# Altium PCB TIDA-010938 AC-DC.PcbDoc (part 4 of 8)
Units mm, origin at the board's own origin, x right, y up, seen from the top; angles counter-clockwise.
Board outline 280 x 180.15 mm, 4 copper layers (Top Layer, Layer 1, Layer 2, Bottom Layer), stack 1.787 mm thick; 723 components, 427 nets, 2244 pads, 2295 vias.
Unrouted connection lines stored in the file: 17.
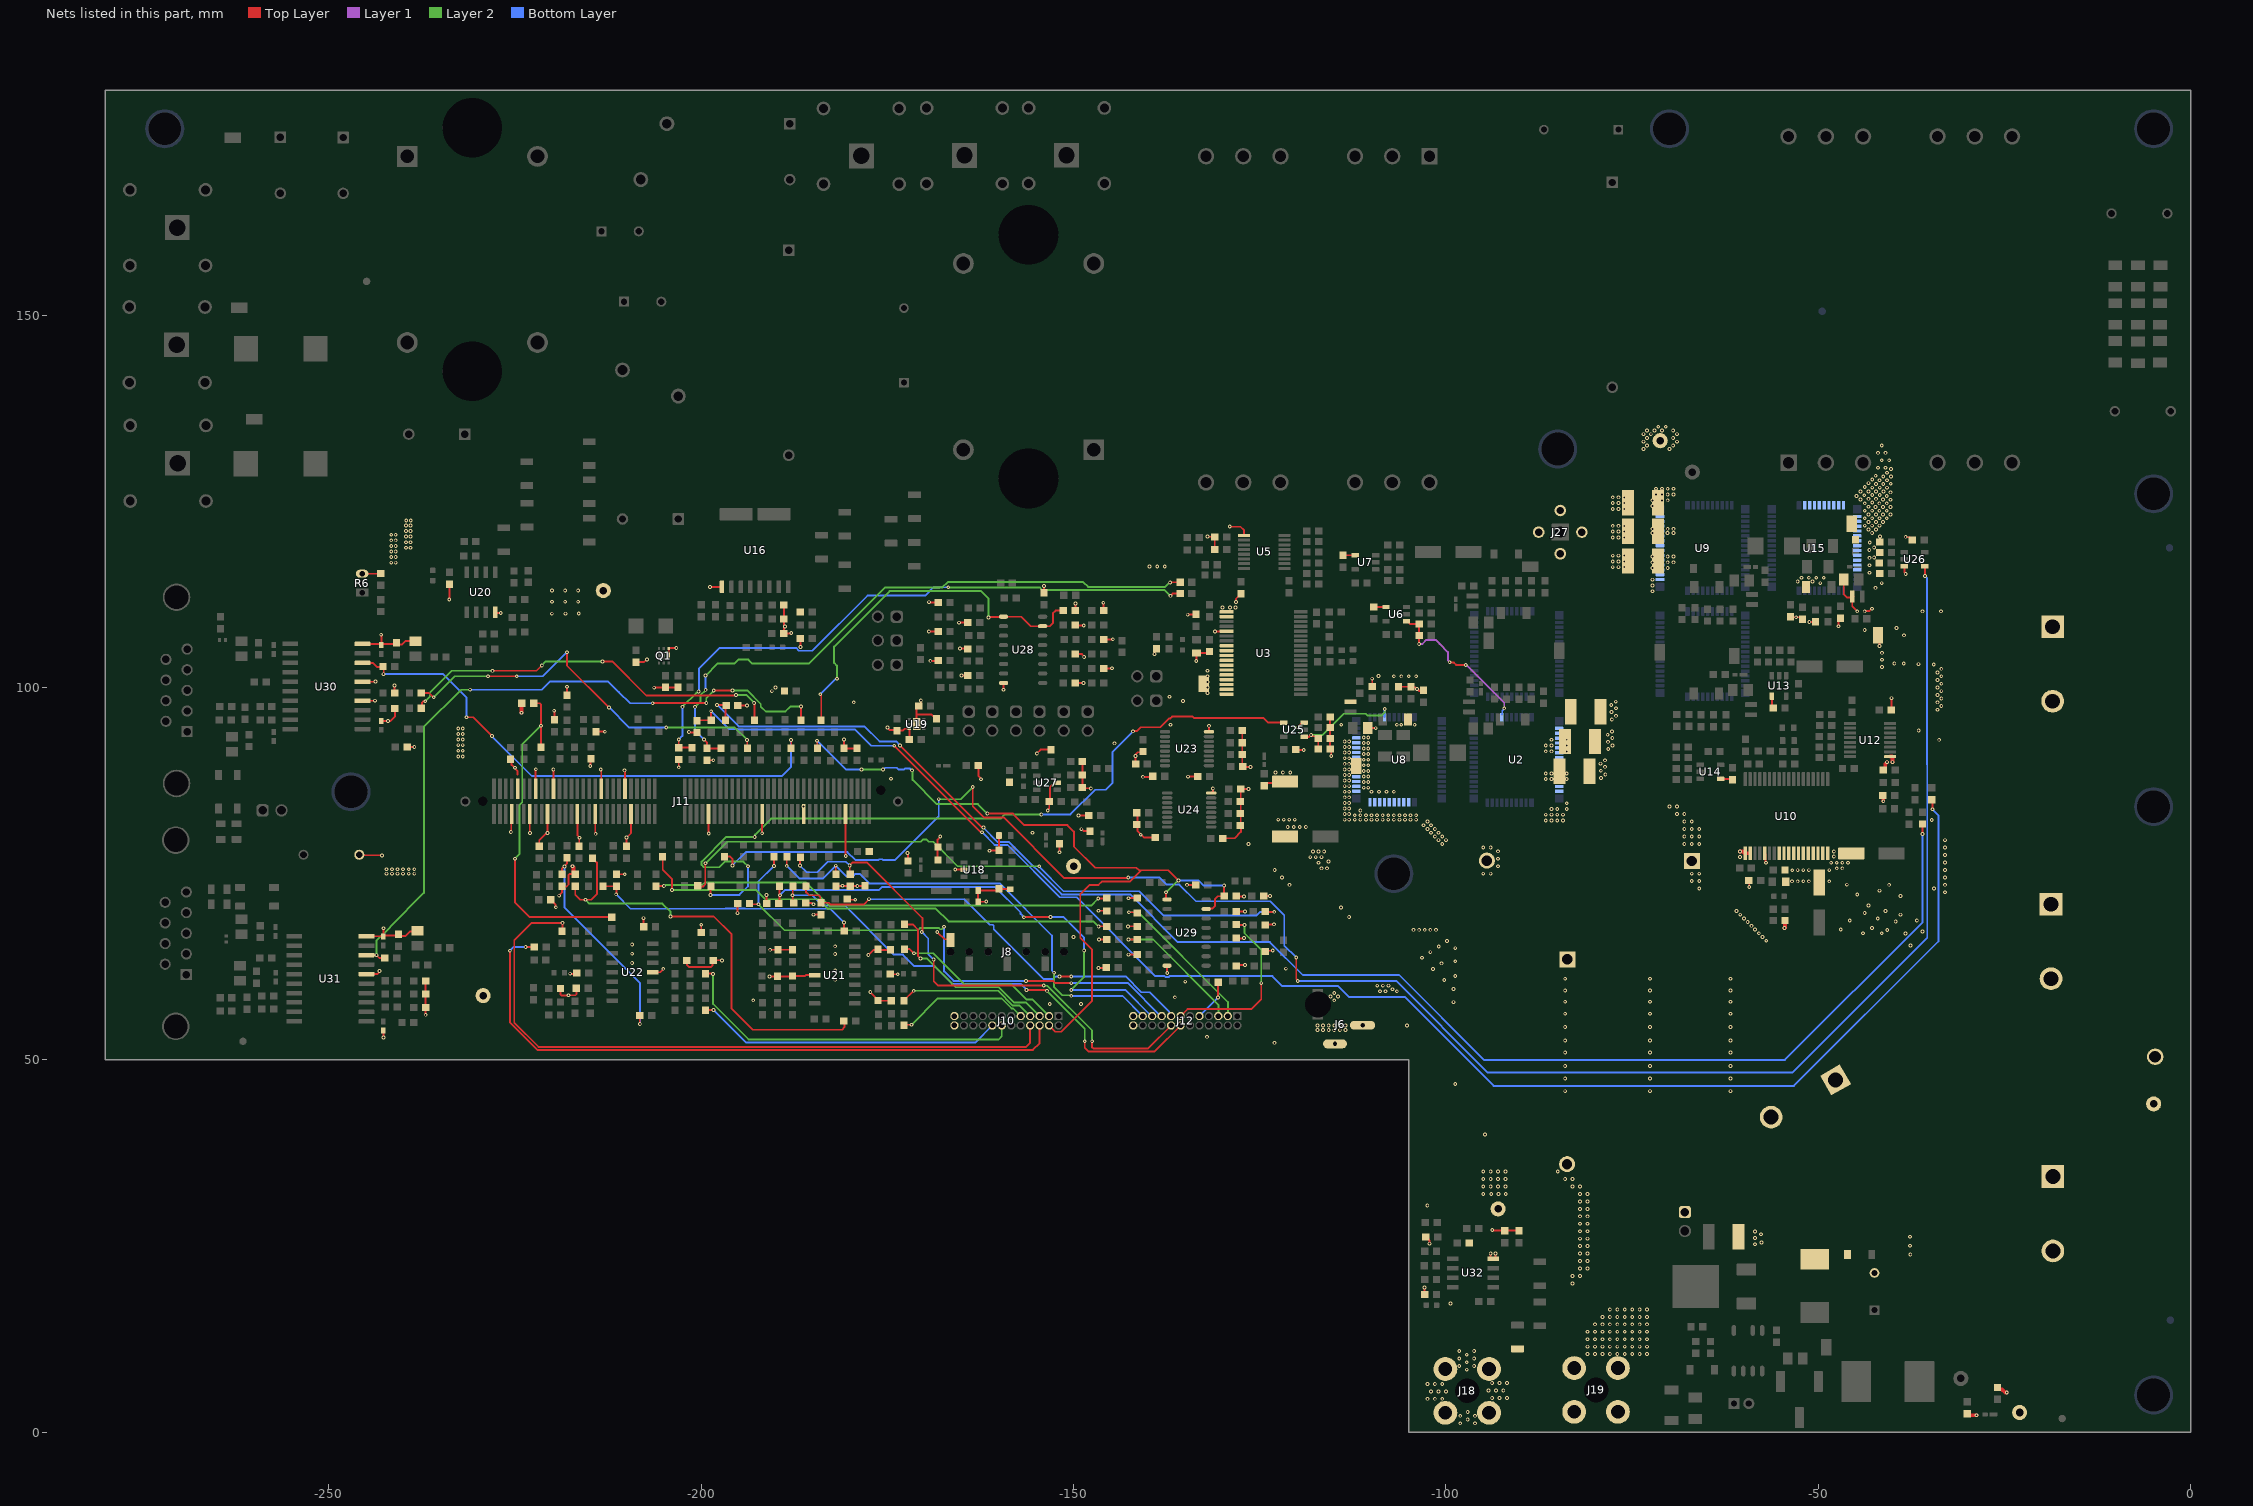
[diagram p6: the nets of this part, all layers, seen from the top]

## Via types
v1: diameter 0.508, hole 0.254, Top Layer to Bottom Layer, tented both sides, 2041 vias
v2: diameter 0.508, hole 0.254, Top Layer to Bottom Layer, 252 vias
v3: diameter 0.5, hole 0.2, Top Layer to Bottom Layer, 2 vias

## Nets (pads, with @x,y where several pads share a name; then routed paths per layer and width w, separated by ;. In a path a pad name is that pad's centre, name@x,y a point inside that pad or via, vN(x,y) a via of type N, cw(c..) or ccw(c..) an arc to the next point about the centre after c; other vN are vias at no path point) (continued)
Batt_L1_Buff: J12.9 R279.2 | length 5.6
  Top Layer w0.25: v1(-130.625,58.365) R279.2@-130.625,60.425
  Bottom Layer w0.25: J12.9@-133.095,55.89 -130.625,58.36 v1(-130.625,58.365)
Batt_L2: R197.2 R282.1 | length 87.2
  Top Layer w0.25: R197.2@-200.479,73.321 R197.2@-200.45,73.35 -200.4,73.3 -199.7,73.3 -199.44,73.56 -199.44,76.281 -199.421,76.3 v1@-199.4,76.3 ; R282.1@-124.249,69.9 -124.225,69.875 -123.125,69.875 v1@-123.075,69.825
  Layer 2 w0.25: v1(-199.4,76.4) -196.517,79.283 -170.516,79.283 -170.194,79.604 -169.756,79.604 -169.434,79.283 -168.859,79.283 -165.577,76 v1(-154.6,76)
  Bottom Layer w0.25: v1@-154.6,75.9 -151.348,72.648 -141.2,72.648 -137.948,69.396 -125.409,69.396 -124.93,69.875 v1(-123.05,69.875)
Batt_L2_Buff: J12.13 R286.2 | length 23.7
  Top Layer w0.25: J12.13@-135.635,55.89 -134.7,56.825 -126.125,56.825 -124.8,58.15 v1(-124.8,60.3) ; R286.2@-128.075,68.125 v1(-127.05,68.125)
  Layer 2 w0.25: v1(-127.05,68.125) -127.05,67.023 -124.8,64.773 v1(-124.8,60.3)
Boost_S1: R198.1 R263.1 | length 62.2
  Top Layer w0.25: R198.1@-206.05,73.325 -206.025,73.35 -205.05,73.35 v1@-205,73.3 ; v1(-146.675,71.675) R263.1@-145.65,71.675
  Layer 2 w0.25: v1(-205,73.35) -204.93,73.35 -204.78,73.5 -199.818,73.5 -199.508,73.81 -185.91,73.81 -182.821,70.721 -147.629,70.721 -146.75,71.6 v1@-146.7,71.6
Boost_S1_Buff: J12.3 R259.2 | length 21
  Top Layer w0.25: v1(-142.575,69.825) -141.75,69.825 R259.2@-141.725,69.85
  Layer 2 w0.25: v1(-142.575,69.825) -141.337,69.825 -129.285,57.773 -129.285,56.06 J12.3@-129.2,55.975
Boost_S2: R199.1 R267.1 | length 65.5
  Top Layer w0.25: R199.1@-205.2,77.25 -205.15,77.2 -205.15,75.497 -203.9,74.247 v1(-203.9,72.8) ; v1@-146.7,67.9 -146.663,67.937 R267.1@-145.531,67.937
  Layer 2 w0.25: v1(-203.9,72.8) -203.871,72.829 -192.652,72.829 -191.394,71.571 -184.237,71.571 -182.987,70.321 -168.5,70.321 -166.779,68.6 -147.325,68.6 v1(-146.625,67.9)
Boost_S2_Buff: J12.5 R264.2 | length 18.1
  Top Layer w0.25: v1(-142.625,66.175) -141.7,66.175 R264.2@-141.675,66.2
  Layer 2 w0.25: v1@-142.55,66.175 -139.33,66.175 -130.555,57.4 J12.5@-130.555,55.89
CAN_RX: R213.2 R314.1 | length 53.4
  Top Layer w0.25: R314.1@-237.544,99.238 -236.515,99.238 -235.956,98.679 v1(-235.886,98.679) ; v1(-228.588,101.5) v1(-224.75,101.5) ; v1(-218,104.729) -218,102.943 v1(-212.374,97.317) ; v1@-193.8,92.9 -193.8,91.882 R213.2@-193.782,91.864
  Layer 2 w0.25: v1(-235.886,98.679) -233.065,101.5 v1(-228.588,101.5) ; v1@-204.6,94.6 -204.596,94.604 -195.479,94.604 v1(-193.825,92.95)
  Bottom Layer w0.25: v1(-224.75,101.5) -221.25,101.5 -218.021,104.729 v1(-218,104.729) ; v1@-212.4,97.4 -209.617,94.617 v1(-204.674,94.617)
CAN_TX: R215.2 R311.1 | length 52.7
  Top Layer w0.25: R311.1@-237.544,97.206 -237.48,97.27 -237.48,97.928 -237.313,98.096 -237.078,98.096 v1(-237.029,98.146) ; v1(-228.012,102.235) -222.094,102.235 v1(-221.383,102.946) ; v1(-213.25,103.5) -211.913,103.5 -207.334,98.921 -195.561,98.921 -195.532,98.951 -195.349,98.951 v1(-195.3,99) ; R215.2@-192.816,95.598 -192.816,97.884 v1@-192.8,97.9
  Layer 2 w0.25: v1(-237.029,98.146) -236.415,98.76 -236.415,99.305 -233.47,102.25 -228.027,102.25 v1(-228.012,102.235) ; v1(-221.383,102.946) -220.829,103.5 v1(-213.25,103.5) ; v1(-195.3,99) -193.957,99 v1(-192.874,97.917)
CS_Batt1: C146.1 R141.2 R179.2 | length 45.6
  Top Layer w0.25: v1(-225,77) -225,71.156 -223.186,69.342 -223.019,69.175 R141.2@-212.175,69.175 ; C146.1@-222.45,97.875 -221.646,97.875 -221.5,97.729 v1(-221.5,94.853) -221.5,91.978 R179.2@-221.501,91.977
  Layer 2 w0.25: v1(-225,77) -224.4,77.6 -224.4,84.205 -224,84.605 -224,92.353 v1(-221.5,94.853)
CS_Batt1+: J10.6 R139.1 | length 88.4
  Top Layer w0.25: v1(-225.675,64.65) -225.675,55.034 -221.991,51.35 -155.45,51.35 -154.555,52.245 J10.6@-154.555,54.62 ; v1@-223.45,65.175 -223.448,65.173 R139.1@-222.397,65.173
  Bottom Layer w0.25: v1(-225.675,64.65) -225.15,65.175 v1@-223.575,65.175
  other v1: -223.55,65.175
CS_Batt1-: J10.8 R143.1 | length 92.7
  Top Layer w0.25: R143.1@-218.657,67.276 -218.6,67.333 v1@-218.6,68.275 ; v1@-218.65,68.45 -218.7,68.4 -222.725,68.4 -225.075,66.05 -225.075,55 -221.825,51.75 -156.35,51.75 -155.825,52.275 J10.8@-155.825,54.62
  other v1: -218.6,68.4
CS_Batt2: C158.1 R161.2 R184.2 | length 28.7
  Top Layer w0.25: C158.1@-218.675,74.925 -218.488,74.925 C158.1@-218.449,74.886 ; C158.1@-218.675,75.3 -218.675,75.675 -218.025,76.325 R184.2@-218.025,77.125 ; R161.2@-208.226,55.933 -208.226,54.926 v1@-208.2,54.9
  Bottom Layer w0.25: v1(-218.35,75.975) -218.35,70.463 -208.225,60.337 -208.225,54.85 v1@-208.2,54.825
  other v1: -208.225,54.825
CS_Batt2+: J10.14 R159.1 | length 47.4
  Top Layer w0.25: R159.1@-199.435,61.58 -198.43,61.58 v1(-198.4,61.55)
  Layer 2 w0.25: v1@-198.425,61.525 -198.4,61.5 -198.4,57.523 -193.614,52.737 -160.063,52.737 -159.635,53.165 J10.14@-159.635,54.62
CS_Batt2-: J10.16 R163.1 | length 41.3
  Top Layer w0.25: R163.1@-199.435,56.678 -198.322,56.678 v1@-198.3,56.7
  Bottom Layer w0.25: v1@-198.359,56.616 -198.241,56.616 -193.95,52.325 -163.2,52.325 J10.16@-160.905,54.62
  other v1: -198.325,56.7
CS_Boost1: C145.2 R140.2 R187.1 | length 59.3
  Top Layer w0.25: C145.2@-216.85,73.375 C145.2@-216.896,73.329 -216.896,72.146 -216.25,71.5 -214.75,71.5 -213.996,72.254 -213.996,76.487 -214.585,77.076 R187.1@-214.585,77.101 ; v1(-204.088,69.25) -198.3,69.25 -195.9,66.85 -195.9,56.884 -193.066,54.05 -181.075,54.05 -180.75,54.375 -180.75,55.423 R140.2@-180.801,55.474
  Layer 2 w0.25: v1(-215.5,71.5) -214.993,70.993 -205.203,70.993 -204.089,69.879 v1(-204.088,69.25)
CS_Boost1+: J10.7 R3.1 | length 18.9
  Top Layer w0.25: R3.1@-172.775,57.95 -172.775,57.975 -171.475,59.275 v1(-171.45,59.275)
  Layer 2 w0.25: v1(-171.45,59.275) -160.128,59.275 -158.153,57.3 -157.235,57.3 J10.7@-155.825,55.89
CS_Boost1-: J10.9 R4.1 | length 18.1
  Top Layer w0.25: R4.1@-172.75,54.625 -172.65,54.725 v1(-171.75,54.725)
  Layer 2 w0.25: v1@-171.725,54.725 -168.2,58.25 -159.669,58.25 -158.319,56.9 -158.105,56.9 J10.9@-157.095,55.89
CS_Boost2: C151.2 R150.2 R188.1 | length 36
  Top Layer w0.25: R188.1@-213.153,73.316 C151.2@-211.491,73.316 ; v1@-211.375,72.25 C151.2@-211.375,73.316 ; v1(-180.8,68.45) -180.8,67.55 R150.2@-180.65,67.4
  Bottom Layer w0.25: v1(-211.4,72.225) -209.475,70.3 -196.72,70.3 -196.717,70.303 -194.079,70.303 -194.076,70.3 -190.123,70.3 -182.65,70.3 -180.85,68.5 v1@-180.85,68.475
CS_Boost2+: J10.3 R137.1 | length 23.1
  Top Layer w0.25: R137.1@-172.7,64.875 -171.983,64.875 v1(-171.433,64.325)
  Layer 2 w0.25: v1(-171.433,64.325) -168.825,64.325 -164.659,60.159 -158.359,60.159 -156.3,58.1 -155.495,58.1 J10.3@-153.285,55.89
CS_Boost2-: J10.5 R138.1 | length 25.3
  Top Layer w0.25: R138.1@-172.7,68.2 -171.6,68.2 -170.904,67.504 -170.904,63.954 v1(-170.55,63.6)
  Layer 2 w0.25: v1(-170.55,63.6) -169.648,63.6 -165.807,59.759 -160.046,59.759 -157.987,57.7 -156.365,57.7 J10.5@-154.555,55.89
"DC Bus+": C2.2 C3.2 C4.2 C5.2 C30.1 C31.1 C46.1 C76.1 C88.1 C90.1 C241.2 C242.2 J7.1 J18.1 R108.1 TP13.1 U2.2 U2.3 U2.4 U2.5 U2.6 U2.7 U2.8 U2.9 U2.10 U2.11 U2.12 U2.13 U2.14 U2.15 U9.2 U9.3 U9.4 U9.5 U9.6 U9.7 U9.8 U9.9 U9.10 U9.11 U9.12 U9.13 U9.14 U9.15
  other v1: -98.089,1.214 -96.089,1.214 -97.089,1.714 -98.089,2.214 -96.089,2.214 -97.089,2.714 -102.5,4.5 -101.5,4.5 -100.5,4.5 -93.802,4.625 -92.802,4.625 -91.802,4.625 -102,5.5 -101,5.5 -100,5.5 -94.302,5.625 -93.302,5.625 -92.302,5.625 -102.5,6.5 -101.5,6.5 -100.5,6.5 -93.802,6.625 -92.802,6.625 -91.802,6.625 -97.214,8.411 -98.214,8.911 -96.214,8.911 -97.214,9.411 -98.214,9.911 -96.214,9.911 -97.214,10.411 -98.214,10.911 -96.214,10.911 -83,20 -83,21 -82,21 -82,22 -81,22 -82,23 -81,23 -82,24 -81,24 -82,25 -81,25 -82,26 -81,26 -82,27 -81,27 -82,28 -81,28 -82,29 -81,29 -82,30 -81,30 -82,31 -81,31 -82,32 -81,32 -83,33 -82,33 -84,34 -83,34 -85,35 -95,75 -94,75 -93,76 -93,77 -93,78 -95,78.5 -94,78.5 -86.61,82.15 -85.835,82.15 -85.06,82.15 -84.285,82.15 -86.61,82.925 -85.835,82.925 -85.06,82.925 -84.285,82.925 -85.835,83.7 -85.06,83.7 -83.785,83.7 -83.785,84.45 -86.61,87.7 -85.835,87.7 -83.785,87.7 -86.61,88.45 -85.835,88.45 -83.785,88.45 -86.61,91.425 -85.835,91.425 -83.785,91.425 -86.61,92.2 -85.835,92.2 -83.785,92.2 -85.835,92.975 -83.785,92.975 -72.29,112.921 -72.29,113.696 -72.29,114.471 -72.29,116.021 -70.24,116.021 -72.29,116.796 -70.24,116.796 -69.465,116.796 -72.29,117.571 -70.24,117.571 -69.465,117.571 -72.3,120.725 -70.25,120.725 -69.45,120.725 -72.29,121.296 -70.24,121.296 -69.465,121.296 -72.29,124.371 -72.29,125.121 -71.015,125.121 -70.24,125.121 -71.79,125.896 -71.015,125.896 -70.24,125.896 -69.465,125.896 -71.79,126.671 -71.015,126.671 -70.24,126.671 -69.465,126.671
"DC Bus-": C1.2 C2.1 C3.1 C4.1 C5.1 C7.1 C9.1 C10.2 C18.1 C22.2 C23.1 C29.1 C30.2 C31.2 C36.1 C37.1 C38.2 C41.1 C42.1 C46.2 C49.2 C50.1 C51.1 C52.1 C53.1 C54.2 C55.1 C56.1 C64.1 C67.2 C68.1 C76.2 C81.2 C82.1 C83.1 C84.1 C86.1 C87.1 C88.2 C90.2 C92.1 C93.1 C94.2 C95.1 C96.1 C97.1 C98.1 C99.2 C101.1 C105.2 C107.1 C108.1 C109.2 C110.2 C111.2 C112.1 C113.1 C114.2 C115.2 C118.2 C119.2 C120.2 C121.2 C122.1 C123.1 C124.2 C125.1 C126.2 C127.1 C128.1 C129.2 C130.1 C131.1 C132.1 C133.1 C134.1 C135.1 C136.1 C137.1 C138.2 C141.1 C142.1 C145.1 C146.2 C150.2 C151.1 C152.1 C156.2 C157.1 C158.2 C161.1 C162.2 C163.1 C164.1 C165.1 C167.1 C168.1 C169.2 C170.1 C171.1 C172.1 C173.1 C174.1 C175.1 C176.2 C177.1 C178.1 C179.1 C180.1 C181.1 C182.2 C185.2 C186.2 C189.1 C190.1 C191.2 C192.1 C193.1 C194.1 C195.2 C196.1 C197.2 C199.1 C200.1 C201.1 C202.1 C203.2 C204.1 C206.1 C208.1 C209.1 C214.1 C215.2 C216.2 C218.1 C219.1 C222.2 C229.2 C230.1 C231.1 C232.1 C234.1 C235.1 C238.2 C239.2 C241.1 C242.1 C251.2 C252.2 C253.1 C254.1 C255.1 C256.1 D19.2 D20.2 J6.2 J6.3 J8.7 J10.23 J10.24 J11.7 J11.10 J11.13 J11.16 J11.19 J11.22 J11.29 J11.35 J11.38 J11.46 J11.47 J11.65 J11.83 J11.97 J11.111 J12.23 J12.24 J19.1 J27.2 J27.3 J27.4 J27.5 L5.1 L9.1 Q1.4 Q1.7 R2.2 R6.2 R14.1 R16.1 R40.1 R43.1 R48.1 R50.2 R68.2 R70.1 R74.1 R76.1 R90.2 R92.1 R100.2 R101.1 R102.1 R106.2 R107.1 R115.1 R119.2 R133.1 R147.1 R157.1 R167.1 R172.2 R177.1 R202.1 R252.1 R253.1 R254.1 R256.1 R297.1 R298.1 R299.1 R300.1 R301.1 R302.1 R303.1 R304.1 R305.1 R306.1 R307.1 R308.1 R335.1 R336.1 R337.1 R338.1 TP2.1 TP3.1 TP11.1 TP12.1 TP14.1 TP15.1 TP16.1 TP19.1 TP20.1 TP21.1 TP22.1 U3.1 U3.2 U3.5 U3.8 U3.9 U3.10 U3.11 U3.12 U3.13 U3.14 U3.15 U3.16 U3.17 U3.18 U5.9 U8.18 U8.19 U8.20 U8.21 U8.22 U8.23 U8.24 U8.25 U8.26 U8.28 U8.29 U8.30 U8.31 U8.32 U8.33 U8.34 U8.35 U8.36 U8.37 U8.38 U8.39 U10.1 U10.2 U10.5 U10.8 U10.9 U10.10 U10.11 U10.12 U10.13 U10.14 U10.15 U10.16 U10.17 U10.18 U12.9 U15.18 U15.19 U15.20 U15.21 U15.22 U15.23 U15.24 U15.25 U15.26 U15.28 U15.29 U15.30 U15.31 U15.32 U15.33 U15.34 U15.35 U15.36 U15.37 U15.38 U15.39 U16.3 U18.2 U19.3 U19.7@-171.06,95.076 U20.4 U21.11 U22.11 U23.8 U24.8 U25.3 U26.3 U27.2 U28.8 U29.8 U30.4 U30.6 U30.10 U31.6 U31.10 U32.4 | length 331.7
  Top Layer w0.25: C1.2@-245.916,77.54 -245.85,77.474 -242.899,77.474 v1(-242.85,77.425) ; R6.2@-245.5,115.27 -243.03,115.27 C10.2@-243,115.3 ; U30.4@-245.456,98.222 -243.903,98.222 v1@-243.9,98.225 ; U30.6@-245.456,100.762 -243.838,100.762 v1@-243.8,100.8 ; U30.10@-245.456,105.842 -243.078,105.842 C195.2@-242.916,105.68 ; U31.6@-244.92,61.519 -243.481,61.519 v1@-243.1,61.9 ; U31.10@-244.92,66.599 -242.693,66.599 C216.2@-242.658,66.564 ; C197.2@-242.975,95.4 -242.875,95.5 -241.675,95.5 -241.1,96.075 ; v1@-242.925,107.1 -242.916,107.091 C195.2@-242.916,105.68 ; v1@-242.675,53.025 -242.658,53.042 C222.2@-242.658,53.934 ; v1@-242.675,67.525 -242.658,67.508 C216.2@-242.658,66.564 ; v1@-241.175,100.15 -241.175,99.309 C219.1@-241.1,99.234 ; C218.1@-241.1,97.169 -241.075,97.144 -241.075,96.125 ; C189.1@-241.075,105.875 -241.133,105.817 -242.779,105.817 C195.2@-242.916,105.68 ; C189.1@-240.873,105.817 -240.806,105.75 -240.175,105.75 -239.675,106.25 C191.2@-238.6,106.25 ; C214.1@-240.676,66.701 -242.521,66.701 C216.2@-242.658,66.564 ; C214.1@-240.615,66.701 -240.564,66.65 -239.675,66.65 -239.075,67.25 C215.2@-238.075,67.25 ; R50.2@-239.45,92 v1(-238.5,92) ; v1@-237,56.1 -236.99,56.11 C235.1@-236.99,57.041 ; C235.1@-236.99,57.16 C232.1@-236.99,58.819 C234.1@-236.99,60.597 ; v1(-233.803,111.811) -233.778,111.836 C230.1@-233.778,113.868 ; U20.4@-227.645,109.675 U20.4@-227.645,109.825 ; U20.4@-227.645,110.075 U20.4@-227.645,109.825 ; v1(-226.9,110) -227.47,110 U20.4@-227.645,109.825 ; C133.1@-225.565,90.339 -225.435,90.209 -225.435,89.61 -224.65,88.825 -224.65,88.325 ; v1(-225.539,80.589) -225.49,80.639 -225.49,82.915 J11.7@-225.407,82.998 ; J11.13@-223.007,82.998 -223.007,80.482 v1@-223,80.475 ; v1@-222.225,88.9 -222.207,88.882 J11.16@-222.207,86.398 ; C152.1@-221.725,78.7 -221.725,79.475 -220.799,80.401 -220.744,80.401 -220.7,80.445 v1@-220.7,80.5 ; v1@-220.607,80.507 J11.19@-220.607,82.998 ; C92.1@-220.2,71.5 -220.175,71.5 -219.549,70.874 -219.549,70.549 v1(-219.5,70.5) ; J11.22@-219.807,86.398 -219.807,88.918 v1@-219.8,88.925 ; C112.1@-219.698,95.672 -219.675,95.695 v1@-219.675,96.825 ; v1(-219.05,72.05) -219.05,72.075 -218.675,72.45 C158.2@-218.675,73.325 -218.6,73.25 -218.096,73.25 -217.8,73.546 -217.8,74.8 -217.65,74.95 C145.1@-217.25,74.95 ; R147.1@-218.873,59.576 -218.873,58.771 -218.727,58.625 -218.42,58.625 ; -218.419,58.626 v1@-217.925,58.626 ; C107.1@-217.975,98.975 -218,99 -218,100.075 v1@-217.975,100.1 ; v1(-217.8,58.675) -216.871,58.675 -216.725,58.821 -216.725,59.268 -216.6,59.393 C150.2@-216.6,59.425 ; v1@-217.6,61.525 -216.821,61.525 C142.1@-216.696,61.65 ; J11.29@-216.607,82.998 -216.607,80.177 -216.325,79.895 v1@-216.325,79.85 ; C157.1@-216.363,78.701 v1@-216.363,79.825 ; v1@-214.854,89.46 -214.854,90.371 C132.1@-214.8,90.425 ; J11.35@-214.207,82.998 -214.207,80.482 v1@-214.2,80.475 ; C134.1@-214.099,94.07 -212.97,94.07 v1@-212.95,94.05 ; J11.38@-213.407,86.398 -213.407,88.893 v1@-213.4,88.9 ; C151.1@-211.375,74.916 -210.334,74.916 v1@-210.325,74.925 ; J11.46@-210.207,86.398 -210.207,88.793 v1@-210.2,88.8 ; C164.1@-210.013,78.701 -210,78.714 v1@-210,79.8 ; v1@-209.95,79.925 -209.925,79.925 -209.407,80.443 J11.47@-209.407,82.998 ; C105.2@-208.75,103.4 -207.67,103.4 -207.32,103.75 v1(-207.25,103.75) ; C165.1@-207.718,67.871 -207.718,68.882 v1@-207.7,68.9 ; U22.11@-206.504,61.775 -205.475,61.775 v1@-205.05,62.2 ; v1(-206.3,99.975) -204.8,99.975 C114.2@-204.775,100 R90.2@-203.225,100 ; Q1.7@-204.35,104.345 Q1.4@-204.35,105.2 ; Q1.4@-204.35,105.225 -204.35,105.25 -204.325,105.275 v1@-203.3,105.275 ; R90.2@-203.175,100.05 R90.2@-203.125,100 ; v1(-203,89.275) -202.997,89.278 C37.1@-202.997,90.326 ; C163.1@-201.937,63.32 -201.9,63.283 -201.9,62.771 -201.579,62.45 -198.7,62.45 -198.45,62.7 -198.45,63.05 R172.2@-198.475,63.075 ; v1@-201.668,94.027 -201.591,93.95 C83.1@-200.575,93.95 ; C161.1@-199.981,67.13 -199.981,68.169 v1@-199.975,68.175 ; C36.1@-199.2,90.25 -199.174,90.224 v1(-198.359,90.224) ; J11.65@-199.007,82.998 -199.007,80.457 v1@-199,80.45 ; v1(-198.8,113.5) -197.211,113.5 U16.3@-197.195,113.516 ; R172.2@-198.381,63.32 -198.326,63.375 v1@-197.225,63.375 ; v1(-195.1,69.7) C136.1@-195.1,71 ; C82.1@-195.05,97.55 -195.025,97.575 v1(-193.825,97.575) ; v1@-191.825,80.425 -191.807,80.443 J11.83@-191.807,82.998 ; v1(-191.2,72.125) -191.2,71.25 C137.1@-191.175,71.225 ; v1@-190.8,64.8 -190.781,64.781 -187.781,64.781 C156.2@-187.725,64.725 ; v1@-190.75,61.275 -190.75,61.244 -190.706,61.2 -187.805,61.2 C162.2@-187.738,61.267 -186.058,61.267 -185.925,61.4 -185.325,61.4 U21.11@-185.3,61.425 ; C111.2@-188.89,107.263 -187.988,107.263 v1@-187.975,107.25 ; C111.2@-188.877,107.373 v1@-188.877,108.189 ; C109.2@-188.877,111.051 v1@-188.877,108.189 ; v1(-188.75,108.189) v1@-188.877,108.189 ; v1(-186.65,105.45) -186.65,106.5 C115.2@-186.525,106.625 ; v1(-186.25,84) -186.228,83.978 -186.228,83.019 J11.97@-186.207,82.998 ; C130.1@-185.975,71.075 -185.145,71.075 -184.97,70.9 v1(-184.9,70.9) ; v1(-184.9,69.5) C135.1@-183.9,69.5 ; C231.1@-181.9,73.325 v1@-180.95,73.325 ; v1@-180.975,73.35 v1@-180.95,73.325 ; v1(-180.825,93) -180.825,92 C182.2@-180.775,91.95 ; C182.2@-180.775,91.826 -179.251,91.826 C181.1@-179.151,91.726 ; v1@-180.675,77.425 -180.66,77.425 -180.591,77.494 -180.591,82.982 J11.111@-180.607,82.998 ; C108.1@-180.4,71.6 -180.3,71.5 v1(-179.3,71.5) ; v1@-179.025,73.325 C131.1@-179.975,73.325 v1@-180.95,73.325 ; v1(-179.025,73.35) -178.35,73.35 C113.1@-178.3,73.4 ; v1@-177.575,64.025 -176.825,64.775 R119.2@-174.55,64.775 ; v1@-177.2,58.95 -177.175,58.95 -176.225,58 C7.1@-176.225,57.975 -176.2,57.95 R2.2@-174.475,57.95 ; v1(-174.973,94.607) -174.973,94.573 -174.675,94.275 C123.1@-173.725,94.275 ; C141.1@-174.595,61.512 -174.583,61.5 v1(-173.6,61.5) ; C123.1@-173.725,94.201 -172.899,94.201 -172.65,94.45 U19.3@-172.035,94.45 ; R70.1@-172.2,76.7 v1@-172.2,77.8 ; C29.1@-172.05,93 -172.035,93.015 U19.3@-172.035,94.426 ; v3(-171.06,95.626) -171.06,96.368 ; v1(-170.5,98.25) -170.5,97.8 R16.1@-170.8,97.5 -171.06,97.24 -171.06,96.368 ; v1@-169.4,107.525 -169.397,107.522 R301.1@-168.185,107.522 ; v1@-169.375,111.4 -169.37,111.405 R302.1@-168.185,111.405 ; v1@-169.2,103.575 -168.249,103.575 R300.1@-168.185,103.639 ; C122.1@-168.596,95.876 -168.596,95.901 -168.946,96.251 -168.971,96.251 -169.088,96.368 -171.06,96.368 ; v1@-168.2,67.1 -167.3,66.2 J8.7@-166.24,66.2 ; C127.1@-168.197,76.819 -168.25,76.872 -168.25,79.58 -167.9,79.93 v1(-167.9,80) ; v1@-165.85,75.525 -165.826,75.549 U18.2@-164.708,75.549 ; v1@-165.35,108.725 C192.1@-164.175,108.725 ; v1(-165.246,105.225) -164.231,105.225 C194.1@-164.175,105.169 ; v1(-165.028,101.6) -164.188,101.6 C196.1@-164.175,101.613 ; R76.1@-162.779,89.5 -162.779,88.12 -162.404,87.745 v1(-162.404,87.675) ; v1@-161.825,71.25 -161.844,71.231 C124.2@-162.812,71.231 C120.2@-162.812,72.755 -160.27,72.755 C125.1@-160.05,72.975 ; v1@-161.2,78.1 -161.173,78.127 R106.2@-160.03,78.127 C126.2@-160.03,80.055 ; C126.2@-160.075,80.166 C126.2@-160.03,80.121 ; C125.1@-160.03,72.971 -159.984,72.925 -158.55,72.925 C121.2@-158.425,72.8 ; v1(-159.407,99.695) -159.403,99.698 -159.403,100.602 U28.8@-159.4,100.605 ; v1(-154.925,91.152) -154.427,91.65 C98.1@-153.025,91.65 ; v1(-153.975,113.62) -153.975,112.729 C201.1@-153.971,112.725 ; v1(-153.465,83.483) -153.465,83.553 -153.26,83.758 C93.1@-153.26,84.69 -153.15,84.8 -153.15,86.675 -152.6,87.225 U27.2@-152.2,87.225 ; v1@-151.9,77.9 R101.1@-151.9,79 ; C200.1@-149.753,100.604 -148.679,100.604 v1(-148.675,100.6) ; C204.1@-149.753,104.487 -149.741,104.475 -148.878,104.475 -148.624,104.221 -148.624,104.145 v1(-148.575,104.096) ; C206.1@-149.753,108.37 -149.683,108.3 v1@-148.675,108.3 ; R254.1@-149.753,110.312 -149.753,111.272 v1@-149.725,111.3 ; v1(-149.35,82.825) -148,82.825 C52.1@-147.975,82.8 ; v1(-148.95,80.975) -148.888,80.975 -148.65,80.737 -147.862,80.737 R102.1@-147.8,80.675 ; C101.1@-148.8,90.05 R256.1@-148.8,88.25 R252.1@-148.8,86.55 -148.717,86.467 v1@-147.679,86.467 ; v1@-146.65,62.35 -145.643,62.35 R306.1@-145.607,62.386 ; v1@-146.6,66.15 -146.591,66.159 R307.1@-145.531,66.159 ; v1@-146.6,70.025 -145.587,70.025 R308.1@-145.531,69.969 ; R299.1@-146,102.601 R299.1@-145.943,102.544 -144.906,102.544 v1@-144.9,102.55 ; v1@-146,111.35 -146,110.367 R297.1@-145.943,110.31 ; R298.1@-145.943,106.427 -144.773,106.427 v1(-144.725,106.475) ; v1@-142.65,67.9 -142.613,67.937 C193.1@-141.467,67.937 ; v1@-142.6,64.125 -142.598,64.127 C199.1@-141.467,64.127 ; v1@-142.6,71.75 -142.597,71.747 C190.1@-141.467,71.747 ; C172.1@-141.675,89.725 -141.675,91.025 -141.4,91.3 -140.9,91.3 C173.1@-140.8,91.4 ; C180.1@-141.525,83.175 -141.425,83.075 -141.425,80.75 -140.55,79.875 -139.775,79.875 C176.2@-139.025,79.875 ; v1(-140.7,88) C169.2@-139.625,88 ; v1(-139.114,104.465) -139.114,104.986 R14.1@-138.875,105.225 ; v1@-137.45,61.6 U29.8@-137.45,62.645 ; v1@-134.775,73.45 -134.721,73.504 C203.2@-133.593,73.504 ; v1@-134.625,88.025 -133.375,88.025 C171.1@-133.35,88.05 ; v1@-134.6,109.8 C23.1@-133.55,109.8 ; v1@-133.5,103.7 -133.475,103.725 C18.1@-133.475,104.625 -132.125,104.625 -132,104.75 C22.2@-132,104.9 ; v1@-132.1,120.2 -132.075,120.225 C42.1@-131.05,120.225 -131.05,118.75 C41.1@-131.1,118.7 ; U23.8@-131.825,94.05 v1@-131.825,94.875 ; U24.8@-131.525,85.825 -131.433,85.917 -131.298,85.917 v1(-131.298,86.452) ; v1(-131,107.5) -130.975,107.525 -129.475,107.525 U3.5@-129.45,107.55 ; C178.1@-129.975,79.75 -128.375,79.75 -127.525,80.6 C177.1@-127.525,81.5 ; v1(-129.032,121.615) -128.983,121.566 -127.586,121.566 -127.1,121.08 U5.9@-127.1,120.423 ; v1(-128.194,111.491) -128.201,111.497 -128.201,111.874 -127.5,112.575 C38.2@-127.5,112.6 ; C208.1@-128.183,66.38 -128.103,66.3 v1@-127.175,66.3 ; C209.1@-128.183,69.936 -128.172,69.925 v1(-127,69.925) ; R253.1@-128.183,72.001 -128.107,71.925 v1@-127.15,71.925 ; C202.1@-128.145,62.618 -128.038,62.725 v1@-127.025,62.725 ; C177.1@-127.55,81.5 R202.1@-127.55,86.35 v1@-126.525,86.35 ; C170.1@-127.35,89.375 C167.1@-127.35,92.575 R177.1@-127.35,94.225 ; C170.1@-127.3,89.375 -127.225,89.3 v1@-126.1,89.3 ; R43.1@-124.4,86.8 -124.4,86.825 -124.05,87.175 -121.825,87.175 C238.2@-121.6,87.4 ; R303.1@-124.389,72.001 v1(-123.639,72.001) ; R304.1@-124.246,68.125 -124.171,68.2 v1(-123.1,68.2) ; R305.1@-124.165,64.65 v1@-123.225,64.65 ; C185.2@-120.15,91.625 -120.125,91.6 v1(-119.1,91.6) ; v1(-119.945,94.671) -119.876,94.671 -119.473,95.074 -119.456,95.074 -119.251,95.279 U25.3@-119.051,95.279 ; C253.1@-115.562,93.125 C255.1@-115.562,94.604 R337.1@-115.562,95.804 ; C253.1@-115.55,93.125 R335.1@-115.55,91.725 -115.4,91.575 v1(-115.4,90.8) ; R337.1@-115.55,95.85 R337.1@-115.5,95.8 ; L5.1@-112.825,98.075 -112.525,98.075 L5.1@-112.325,98.275 ; C54.2@-110.209,94.79 -109.999,94.58 -109.999,94.535 v1(-109.435,94.535) ; v1(-109.91,101.183) -109.9,101.173 C51.1@-109.9,100.125 ; v1@-109.099,101.501 v1(-109.05,101.55) ; R40.1@-106.4,100.1 C53.1@-104.7,100.1 -104.6,100 -104.1,100 v1(-103.9,99.8) -103.7,99.6 ; C49.2@-105.1,95.725 C49.2@-105.067,95.758 ; C50.1@-103.4,99.5 -103.6,99.5 -103.7,99.6 ; C50.1@-103.025,99.6 -103.7,99.6 ; v1(-102.892,19.431) -102.892,18.553 C128.1@-102.871,18.532 ; R133.1@-102.739,26.251 R133.1@-102.714,26.251 -102.689,26.251 -102.339,25.901 -102.339,25.876 -102.231,25.768 v1@-102.231,25.273 ; v1(-94,24) -94,23.48 -93.825,23.305 U32.4@-93.675,23.305 -93.525,23.305 -93.35,23.48 v1(-93.35,24.025) ; v1@-93.798,27.102 -93.778,27.081 R68.2@-90.171,27.081 ; C68.1@-59.365,74.071 -59.29,73.996 v1(-59.29,73.221) ; U10.5@-57.215,77.746 -57.115,77.646 -57.115,76.615 -57.04,76.54 v1(-57.04,76.471) ; C95.1@-53.765,109.265 -53.61,109.421 v1(-52.99,109.421) -52.365,109.421 C97.1@-52.115,109.171 ; C94.2@-51.79,114.146 -51.615,113.971 C94.2@-51.54,113.971 ; v1(-51.224,108.777) -50.434,108.777 R74.1@-50.415,108.796 ; v1(-47.29,108.221) -47.29,109.021 C96.1@-47.015,109.296 ; C99.2@-46.606,114.496 -46.606,112.489 -46.205,112.088 L9.1@-45.465,112.088 ; L9.1@-45.465,112.221 L9.1@-45.465,112.088 ; L9.1@-45.29,112.221 -45.423,112.088 L9.1@-45.465,112.088 ; v1(-44.79,110.221) -45.465,110.896 L9.1@-45.465,112.088 ; v1(-43.79,110.221) -43.745,110.265 -43.161,110.265 -42.86,110.567 v1(-42.79,110.567) ; TP22.1@-42,107 -41.8,106.8 v1(-41.8,105.55) ; C84.1@-40.215,96.971 C84.1@-40.24,96.971 -40.204,97.006 v1@-40.204,98.501 ; U26.3@-38.465,116.271 -38.465,115.465 -38.29,115.29 v1(-38.29,115.221) ; v1(-38.29,120.221) -38.22,120.221 -38.17,120.171 -37.74,120.171 C186.2@-37.39,119.821
  Top Layer w0.5: v1(-224.1,96.6) -224.098,96.602 -224.098,97.827 C146.2@-224.05,97.875 ; v1(-217.25,76) -217.25,75.998 -217.121,75.869 -217.121,75.154 C145.1@-216.896,74.929 ; v1(-60.54,77.971) -60.19,77.971 -59.965,77.746 U10.1@-59.815,77.746 U10.2@-59.165,77.746 ; v1(-54.54,67.721) -54.54,67.723 -54.49,67.773 R48.1@-54.49,68.721 ; D20.2@-50.471,22.968 D20.2@-49.54,23.899 ; C86.1@-41.34,85.471 -41.292,85.422 -41.292,84.722 v1(-41.29,84.721) ; C87.1@-41.29,88.921 -41.265,88.921 -41.04,89.146 -41.04,89.718 -40.79,89.968 v1(-40.79,89.971) ; U12.9@-40.34,90.721 -40.092,90.721 -40.042,90.671 -40.042,89.972 v1(-40.04,89.971) ; C119.2@-30.023,2.502 -29.824,2.304 -28.774,2.304 v1(-28.773,2.302) ; R100.2@-25.984,6.02 -25.984,5.995 -25.759,5.77 -25.337,5.77 -24.928,5.361 -24.716,5.361 v1(-24.714,5.359)
  other v1: -81,10.5 -80,10.5 -79,10.5 -78,10.5 -77,10.5 -76,10.5 -75,10.5 -74,10.5 -73,10.5 -81,11.5 -80,11.5 -79,11.5 -78,11.5 -77,11.5 -76,11.5 -75,11.5 -74,11.5 -73,11.5 -81,12.5 -80,12.5 -79,12.5 -78,12.5 -77,12.5 -76,12.5 -75,12.5 -74,12.5 -73,12.5 -81,13.5 -80,13.5 -79,13.5 -78,13.5 -77,13.5 -76,13.5 -75,13.5 -74,13.5 -73,13.5 -80,14.5 -79,14.5 -78,14.5 -77,14.5 -76,14.5 -75,14.5 -74,14.5 -73,14.5 -79,15.5 -78,15.5 -77,15.5 -76,15.5 -75,15.5 -74,15.5 -73,15.5 -78,16.5 -77,16.5 -76,16.5 -75,16.5 -74,16.5 -73,16.5 -99.404,17.282 -37.664,23.876 -37.69,25.044 -58.522,25.248 -102.223,25.333 -57.629,25.476 -58.522,26.086 -37.715,26.264 -57.705,26.594 -58.518,26.975 -93.79,27.162 -102.502,30.464 -94.992,31.979 -93.925,32.004 -92.96,32.004 -91.97,32.004 -95,33 -94,33 -93,33 -92,33 -95,34 -94,34 -93,34 -92,34 -95,35 -94,35 -93,35 -92,35 -94.75,40 -84,45.8 -72.6,45.8 -61.8,45.8 -98.75,46.75 -84,47.5 -72.6,47.5 -61.8,47.5 -84,49.2 -72.6,49.2 -61.8,49.2 -84,51 -72.6,51 -61.8,51 -123.004,52.294 -84,52.6 -72.6,52.6 -61.8,52.6 -242.65,53.025 -132.1,53.1 -117.25,54 -116.5,54 -115.75,54 -115,54 -114.25,54 -113.5,54 -84,54.4 -72.6,54.4 -61.8,54.4 -117.25,54.6 -116.5,54.6 -115.75,54.6 -115,54.6 -114.25,54.6 -113.5,54.6 -105.22,54.62 -236.975,56.05 -84,56.2 -72.6,56.2 -61.8,56.2 -153.2,57.5 -149,57.5 -99,57.75 -84,57.8 -72.6,57.8 -61.8,57.8 -193,58 -115,58 -136.4,58.4 -115.5,58.5 -114.5,58.5 -115,59 -177.278,59.1 -84,59.3 -72.6,59.3 -61.8,59.3 -107.195,59.488 -99,59.5 -135,60.5 -182,60.75 -84,60.9 -72.6,60.9 -61.8,60.9 -190.825,61.2 -98.75,61.25 -217.575,61.575 -137.425,61.675 -243.174,61.917 -182,62 -205.075,62.225 -121.5,62.25 -146.65,62.325 -127,62.725 -209.25,63 -98.75,63.25 -197.2,63.35 -177.55,64.075 -142.625,64.125 -181.997,64.223 -209.25,64.25 -123.25,64.675 -190.725,64.775 -98.75,65 -182,65.25 -37.633,65.367 -209.25,65.5 -57,66 -146.6,66.175 -127.125,66.35 -150,66.5 -57.5,66.5 -38.305,66.985 -58,67 -44,67 -41.5,67 -168.298,67.174 -36.04,67.221 -40.758,67.439 -58.5,67.5 -47,67.5 -242.625,67.675 -42.79,67.721 -142.675,67.925 -59,68 -199.975,68.15 -59.5,68.5 -39.633,68.564 -45.79,68.721 -36.79,68.721 -42.04,68.971 -60,69 -207.75,69.025 -60.5,69.5 -39,69.5 -43.79,69.721 -61,70 -41,70 -146.65,70.025 -43.29,70.721 -161.725,71.25 -142.625,71.7 -127.125,71.95 -39,72 -44.79,72.221 -33,72.5 -41.79,72.721 -66,73 -34.5,73 -181,73.375 -134.75,73.5 -121,73.5 -40.5,73.5 -33,73.5 -46.186,73.524 -53.54,73.971 -52.79,73.971 -51.29,73.971 -48.54,73.971 -67,74 -66,74 -52.029,73.98 -122,74.5 -33,74.5 -210.25,74.925 -242.25,75 -241.5,75 -240.75,75 -240,75 -239.25,75 -238.5,75 -67,75 -66,75 -53.514,75.463 -52.79,75.471 -52.04,75.471 -51.29,75.471 -48.54,75.471 -123,75.5 -33,75.5 -165.875,75.55 -242.25,75.6 -241.5,75.6 -240.75,75.6 -240,75.6 -239.25,75.6 -238.5,75.6 -47.54,75.721 -46.79,75.721 -48.29,76.471 -47.54,76.471 -46.79,76.471 -46.04,76.471 -33,76.5 -115.779,76.629 -60.54,77.221 -47.935,77.302 -180.575,77.375 -33,77.5 -172.275,77.775 -151.875,77.875 -47.935,77.971 -161.275,78.075 -33,78.5 -126.5,79 -100.5,79 -68,79 -67,79 -66,79 -101,79.5 -100,79.5 -33,79.5 -216.325,79.825 -210,79.85 -101.5,80 -100.5,80 -68,80 -67,80 -66,80 -140.975,80.225 -214.15,80.35 -198.975,80.4 -191.8,80.425 -220.625,80.45 -222.975,80.475 -155.5,80.5 -102,80.5 -101,80.5 -102.5,81 -101.5,81 -68,81 -67,81 -66,81 -121.25,81.25 -120.438,81.25 -119.625,81.25 -118.813,81.25 -103,81.5 -102,81.5 -102.5,82 -68,82 -67,82 -34.79,82.221 -122.513,82.25 -121.775,82.25 -121.038,82.25 -120.3,82.25 -113.6,82.25 -113,82.25 -112.25,82.25 -111.5,82.25 -110.75,82.25 -110,82.25 -109.25,82.25 -108.5,82.25 -107.75,82.25 -107,82.25 -106.25,82.25 -105.5,82.25 -104.75,82.25 -104,82.25 -112.25,82.85 -111.5,82.85 -110.75,82.85 -110,82.85 -109.25,82.85 -108.5,82.85 -107.75,82.85 -107,82.85 -106.25,82.85 -105.5,82.85 -104.75,82.85 -104,82.85 -113.6,83 -113,83 -69,83 -68,83 -111.5,83.5 -113.6,83.75 -113,83.75 -70,84 -69,84 -113.6,84.5 -113,84.5 -113.6,85.25 -113,85.25 -113.6,86 -113,86 -110,86 -109,86 -108,86 -107,86 -126.5,86.375 -147.679,86.442 -111.036,86.55 -110.436,86.55 -113.6,86.75 -113,86.75 -111.036,87.3 -110.436,87.3 -113.6,87.5 -113,87.5 -174.5,87.75 -79.184,87.841 -134.65,88.025 -111.036,88.05 -110.436,88.05 -113.6,88.25 -113,88.25 -78.609,88.316 -122.9,88.6 -121.9,88.6 -120.9,88.6 -111.036,88.8 -110.436,88.8 -79.209,88.816 -210.275,88.875 -213.475,88.975 -219.835,88.995 -113.6,89 -113,89 -222.185,89.02 -224.975,89.225 -126.245,89.312 -78.634,89.341 -214.879,89.46 -111.036,89.55 -110.436,89.55 -113.6,89.75 -113,89.75 -79.259,89.766 -78.659,90.216 -111.036,90.3 -110.436,90.3 -113.6,90.5 -113,90.5 -232.6,90.75 -232,90.75 -141.7,90.8 -111.036,91.05 -110.436,91.05 -113.6,91.25 -113,91.25 -232.6,91.5 -232,91.5 -78.219,91.727 -111.036,91.8 -110.436,91.8 -113.6,92 -113,92 -77.644,92.202 -232.6,92.25 -232,92.25 -144.5,92.5 -111.036,92.55 -110.436,92.55 -78.244,92.702 -113.6,92.75 -113,92.75 -33.79,92.971 -232.6,93 -232,93 -77.669,93.227 -111.036,93.3 -110.436,93.3 -78.294,93.652 -232.6,93.75 -232,93.75 -201.643,94.027 -212.925,94.05 -77.694,94.102 -36.54,94.221 -232.6,94.5 -232,94.5 -131.825,94.85 -137,95 -114.065,95 -106.6,95 -106,95 -104.2,95 -242.025,95.5 -77.736,95.715 -77.161,96.19 -77.761,96.69 -219.725,96.875 -34,97 -77.186,97.215 -33.5,97.5 -77.811,97.64 -179.5,98 -34,98 -77.211,98.09 -135.3,98.2 -243.775,98.225 -33.5,98.5 -40.19,98.559 -137.124,98.748 -34,99 -132,99.25 -190.5,99.5 -33.5,99.5 -190,100 -132,100 -34,100 -218,100.1 -241.175,100.275 -33.5,100.5 -132,100.75 -243.725,100.8 -34,101 -132,101.5 -107,101.5 -105.995,101.495 -105,101.5 -104,101.5 -33.5,101.5 -34,102 -132,102.25 -33.5,102.5 -144.85,102.575 -41.45,102.75 -34.515,103.099 -36.547,103.124 -39.811,103.221 -38.54,103.221 -133.525,103.55 -169.225,103.575 -41.475,103.725 -41.475,104.65 -203.325,105.3 -38.5,107 -242.95,107.075 -187.9,107.3 -169.425,107.525 -43.79,107.721 -39.5,108 -148.625,108.325 -165.375,108.7 -134.675,109.775 -220.036,109.906 -218.208,109.906 -216.43,109.931 -36.04,110.221 -33.54,110.221 -130,110.75 -129,110.75 -128.275,110.75 -149.75,111.275 -146,111.375 -169.4,111.45 -220,111.5 -218.25,111.5 -216.5,111.5 -220,113 -218.25,113 -216.5,113 -42.35,113.375 -49.75,114 -41.5,114 -52.79,114.221 -50.79,114.221 -52.29,114.721 -51.29,114.721 -50.29,114.721 -49.29,114.721 -43.15,115.4 -77.615,116.146 -76.84,116.146 -76.065,116.146 -139.798,116.256 -138.756,116.256 -137.75,116.25 -43.15,116.4 -241.6,116.75 -241,116.75 -77.615,116.921 -76.84,116.921 -76.065,116.921 -43.15,117.4 -42.514,117.454 -241.6,117.5 -241,117.5 -77.615,117.696 -76.84,117.696 -76.065,117.696 -241.6,118.25 -241,118.25 -43.166,118.454 -239.6,118.75 -239,118.75 -42.514,118.796 -241.6,119 -241,119 -43.115,119.444 -239.6,119.5 -239,119.5 -241.6,119.75 -241,119.75 -77.615,120.146 -76.84,120.146 -76.065,120.146 -239.6,120.25 -239,120.25 -132.025,120.25 -41.75,120.25 -241.6,120.5 -241,120.5 -42.786,120.717 -77.615,120.921 -76.84,120.921 -76.065,120.921 -239.6,121 -239,121 -43.286,121.217 -42.286,121.217 -77.615,121.696 -76.84,121.696 -76.065,121.696 -43.786,121.717 -42.786,121.717 -41.786,121.717 -239.6,121.75 -239,121.75 -41.338,122.199 -43.286,122.217 -42.286,122.217 -239.575,122.425 -238.975,122.425 -43.786,122.717 -42.786,122.717 -41.786,122.717 -40.822,122.715 -43.286,123.217 -42.286,123.217 -41.322,123.215 -40.322,123.215 -43.786,123.717 -42.786,123.717 -41.822,123.715 -40.822,123.715 -77.615,123.971 -76.84,123.971 -76.065,123.971 -42.322,124.215 -41.322,124.215 -40.322,124.215 -43.268,124.257 -43.786,124.717 -41.822,124.715 -40.822,124.715 -77.615,124.746 -76.84,124.746 -76.065,124.746 -42.768,124.824 -40.322,125.197 -41.322,125.215 -44.353,125.239 -43.268,125.324 -42.268,125.324 -77.615,125.521 -76.84,125.521 -76.065,125.521 -44.87,125.699 -40.822,125.697 -43.853,125.806 -42.768,125.824 -41.768,125.824 -40.322,126.197 -44.353,126.306 -43.268,126.324 -42.268,126.324 -41.268,126.324 -42.768,126.824 -41.768,126.824 -40.805,126.822 -43.776,126.924 -42.268,127.324 -41.305,127.322 -40.289,127.348 -43.276,127.424 -41.805,127.822 -40.805,127.822 -42.776,127.924 -41.305,128.322 -40.271,128.321 -42.313,128.422 -40.805,128.822 -40.246,129.311 -42,129.5 -41,129.5 -41.5,130.5 -40.5,130.5 -42,131.5 -41,131.5 -73.5,132 -70,132 -73,132.5 -69.5,132.5 -41.5,132.5 -73.5,133 -69,133 -73,133.5 -69.5,133.5 -73.5,134 -72.5,134 -69,134 -73,134.5 -72,134.5 -71,134.5 -69.5,134.5 -71.5,135 -70.5,135
  other v2: -108.852,59.215 -108.102,59.215 -106.602,59.215 -109.227,59.965 -108.477,59.965 -107.727,59.965 -100.227,60.715 -101.727,62.215 -100.602,62.965 -103.227,63.715 -102.102,64.465 -100.977,65.215 -99.852,65.965 -104.352,67.465 -103.602,67.465 -102.852,67.465 -102.102,67.465 -101.352,67.465 -113,69.2 -114.102,70.465 -116.727,75.715 -115.977,75.715 -117.102,76.465 -118.227,77.215 -117.477,77.215 -116.727,77.215 -117.852,77.965 -117.102,77.965 -116.352,77.965
  other v3: -171.06,94.526
Enable_Buffer_ACDC: R232.2 R254.2 U28.1 U28.15 | length 49.5
  Top Layer w0.25: v1(-183.996,99.095) -183.996,99.025 -183.876,98.906 R232.2@-183.876,95.598 ; v1(-161.4,109.4) -161.352,109.448 -159.448,109.448 U28.1@-159.4,109.495 -156.995,109.495 -155.725,108.225 -154.525,108.225 U28.15@-154.5,108.2 ; U28.15@-154.15,108.225 -153.175,108.225 -152.775,108.625 -152.775,109.95 -152.4,110.325 -151.675,110.325 R254.2@-151.625,110.375
  Layer 2 w0.25: v1(-181.759,101.168) -181.759,102.926 -182.135,103.302 -182.135,105.491 -174.697,112.928 -162.404,112.928 -161.4,111.925 v1(-161.4,109.4)
  Bottom Layer w0.25: v1(-183.996,99.095) -181.972,101.119 -181.808,101.119 v1(-181.759,101.168)
Enable_Buffer_DCDC: J10.4 R230.2 R253.2 U29.1 U29.15 | length 106.2
  Top Layer w0.25: v1(-184.425,92.85) v1@-184.425,92.92 ; v1@-184.4,92.8 -184.4,91.842 R230.2@-184.384,91.826 ; v1@-161.5,83.1 -161.475,83.075 -158.141,83.075 -156.591,81.525 -150.825,81.525 -149.95,80.65 -149.95,78.65 -147.1,75.8 -141.554,75.8 -141.208,75.454 -140.923,75.454 ; J10.4@-153.285,54.62 -152.45,53.785 -151.669,53.785 -147.5,57.954 -147.5,64.802 -149.1,66.402 -149.1,72.25 -147.85,73.5 -146.648,73.5 -146.202,73.946 -142.431,73.946 -140.923,75.454 ; v1@-137.575,72.425 -137.575,71.66 U29.1@-137.45,71.535 ; v1@-136,74.2 -137.254,75.454 -140.923,75.454 ; U29.15@-132.2,70.265 -132.143,70.322 -131.353,70.322 -131.025,70.65 -131.025,71.575 -130.625,71.975 R253.2@-129.925,71.975 ; R253.2@-129.783,72.001 v1@-129.783,73.333
  Layer 2 w0.25: v1(-178.475,88.975) -175.625,88.975 v1@-175.6,89 ; v1@-171.6,88.9 -171.6,87.6 -168.346,84.346 -162.846,84.346 v1(-161.575,83.075) ; v1(-137.6,72.5) -137.563,72.5 -135.963,74.1 v1(-135.925,74.1)
  Bottom Layer w0.25: v1(-184.425,92.85) -180.575,89 v1@-178.4,89 ; v1(-175.575,88.975) -175.537,88.975 -175.3,89.213 -173.707,89.213 -173.469,88.975 -172.786,88.975 -172.657,89.104 -171.974,89.104 -171.77,88.9 v1@-171.7,88.9 ; v1@-135.9,74.1 -133.222,74.1 -132.522,73.4 v1(-129.775,73.4)
  other v1: -171.675,88.875
Enable_CAN: R224.2 R310.1 U30.8 | length 70.8
  Top Layer w0.25: U30.8@-245.456,103.302 -244.098,103.302 -243.546,102.75 R310.1@-242.975,102.75 ; R310.1@-242.7,102.794 -242.6,102.694 v1@-242.6,101.7 ; v1(-231.5,96) -230.6,96 v1@-228.1,93.5 ; R224.2@-187.94,91.864 -187.9,91.904 v1@-187.9,92.8
  Bottom Layer w0.25: v1(-242.634,101.786) -234.627,101.786 -231.5,98.659 v1(-231.5,96) ; v1@-228.1,93.5 v1(-228.075,93.475) -222.7,88.1 -189.2,88.1 -187.925,89.375 v1(-187.925,92.95)
Enable_RS485: R226.2 R318.1 U31.8 | length 94.8
  Top Layer w0.25: U31.8@-244.92,64.059 v1(-243.584,64.059) -243.203,63.678 R318.1@-242.442,63.678 ; v1@-206.5,97.9 -206.471,97.929 -200.581,97.929 -200.552,97.9 v1(-199.3,97.9) ; v1@-198.274,99.574 v1(-195.798,99.574) ; R226.2@-186.609,95.625 -186.6,95.634 -186.6,97.405 v1(-186.575,97.43)
  Layer 2 w0.25: v1(-243.584,64.059) -243.584,65.968 -241.729,67.823 -241.729,67.9 -237.204,72.425 -237.204,94.696 -232.2,99.7 v1(-231,99.7) ; v1(-199.3,97.9) -199.3,98.572 v1(-198.298,99.574) ; v1@-195.795,99.6 -193.809,99.6 -191.987,97.778 -191.987,97.439 -191.319,96.771 -188.681,96.771 -188.022,97.43 v1(-186.575,97.43)
  Bottom Layer w0.25: v1(-231,99.7) -221.404,99.7 -220.313,100.792 -212.459,100.792 -211.042,99.375 -211.027,99.375 -209.526,97.874 v1(-206.498,97.874)
F\A\U\L\T\_O\C\_Batt_H1_Buff: C137.2 J12.19 R219.1 | length 66.3
  Top Layer w0.25: R219.1@-189.464,73.291 -189.464,71.264 C137.2@-189.425,71.225 ; v1(-156.675,69.152) -156.651,69.176 -153.124,69.176 v1(-153.1,69.2)
  Layer 2 w0.25: v1(-150.3,59.4) -148.6,61.1 v1@-148.6,64.6
  Bottom Layer w0.25: v1(-189.425,72.1) -188.704,72.821 -176.102,72.821 -175.723,73.2 -160.521,73.2 -157.107,69.786 -157.107,69.609 -156.675,69.177 v1(-156.675,69.152) ; v1(-153.1,69.2) -151.4,69.2 -148.575,66.375 v1(-148.575,64.675) ; v1(-150.3,59.4) -143.044,59.4 -139.534,55.89 J12.19@-139.445,55.89
F\A\U\L\T\_O\C\_Batt_H2_Buff: C130.2 J12.14 R223.1 | length 66
  Top Layer w0.25: R223.1@-187.686,73.291 -187.686,71.036 C130.2@-187.575,70.925 ; v1(-156.3,59.4) -153.77,59.4 -153.645,59.275 v1(-153.575,59.275) ; v1(-148.5,52.5) -148.5,51.641 -148,51.141 -139.114,51.141 J12.14@-135.635,54.62
  Layer 2 w0.25: v1@-153.5,59.2 -148.5,54.2 v1(-148.5,52.5)
  Bottom Layer w0.25: v1(-187.725,72.1) -185.1,72.1 -183.737,70.738 -180.738,70.738 -174.129,64.129 -172.904,64.129 -171.375,62.6 -168.666,62.6 -166.266,60.2 -157.1,60.2 v1(-156.3,59.4)
F\A\U\L\T\_O\C\_Batt_L1_Buff: C231.2 J12.21 R221.1 | length 64
  Top Layer w0.25: R221.1@-188.525,77.35 -188.5,77.325 v1(-188.5,76.05) ; v1(-181.925,76.075) -181.925,75 C231.2@-181.9,74.975
  Layer 2 w0.25: v1(-152.6,61.7) -152.626,61.674 -152.626,59.826 -151.484,58.684 v1@-150.316,58.684
  Bottom Layer w0.25: v1(-188.5,76.05) -186.825,74.375 -183.625,74.375 v1@-181.95,76.05 ; v1(-181.925,76.075) -180.504,74.654 -179.602,74.654 -179.295,74.961 -178.709,74.961 -177.449,73.7 -159.9,73.7 -152.9,66.7 -152.9,62 v1(-152.6,61.7) ; v1(-150.3,58.6) -143.425,58.6 J12.21@-140.715,55.89
F\A\U\L\T\_O\C\_Batt_L2_Buff: C131.2 J12.16 R225.1 | length 70.4
  Top Layer w0.25: v1(-186.725,76.1) R225.1@-186.725,77.125 ; C131.2@-179.975,74.925 -180.05,75 v1(-180.05,76.1) -179.646,76.504 -177.756,76.504 -170.3,69.048 v1@-170.3,67.2 ; v1(-168.775,63.475) -168.775,60.575 -168.2,60 v1(-154,60) ; v1(-147.5,52.5) -147.5,51.687 -147.354,51.541 -139.984,51.541 J12.16@-136.905,54.62
  Layer 2 w0.25: v1(-154,60) -153.951,59.951 -153.503,59.951 -147.5,53.948 v1(-147.5,52.5)
  Bottom Layer w0.25: v1(-186.725,76.1) -185.825,75.2 -184.4,75.2 -182.996,76.604 -180.554,76.604 -180.125,76.175 v1@-180.05,76.175 ; v1(-170.375,67.175) -169.5,66.3 -169.5,64.2 v1(-168.775,63.475)
F\A\U\L\T\_O\C\_Boost1_Buff: C135.2 J12.15 R227.1 | length 58.5
  Top Layer w0.25: R227.1@-185.908,73.291 -185.908,73.3 -185.895,73.314 -185.895,72.495 -185.5,72.1 -184.2,72.1 -184,71.9 -184,71.3 C135.2@-183.9,71.2 ; C135.2@-183.9,71.1 -182.864,71.1 -182.614,70.85 -178.15,70.85 v1@-177.4,71.6 ; v1(-151.9,61.2) v1(-150.3,61.2)
  Bottom Layer w0.25: v1(-177.475,71.575) -164.675,71.575 -161.24,68.14 -160.853,68.14 -160.706,67.993 -160.706,67.535 -154.017,60.845 -152.707,60.845 -152.352,61.2 v1(-151.9,61.2) ; v1(-150.3,61.2) -143.008,61.2 -140.887,59.079 -139.779,59.079 -137.159,56.459 -137.159,56.379 -136.905,56.125 J12.15@-136.905,55.89
F\A\U\L\T\_O\C\_Boost2_Buff: C136.2 J12.17 R217.1 | length 72.8
  Top Layer w0.25: C136.2@-193.4,71.1 -193.2,70.9 v1(-192.3,70.9) ; v1(-190.225,76.025) R217.1@-190.225,77.375 ; v1(-156.4,60.6) -152.753,60.6 -152.453,60.3 v1@-150.4,60.3
  Layer 2 w0.25: v1(-192.3,70.9) -188.8,67.4 -170.898,67.4 -170.594,67.704 -168.08,67.704 -167.916,67.541 -167.709,67.541 v1(-167.375,67.875)
  Bottom Layer w0.25: v1(-192.3,70.9) -192.3,73.95 v1(-190.225,76.025) ; v1(-167.375,67.875) -167.375,61.875 -166.1,60.6 v1(-156.4,60.6) ; v1(-150.3,60.3) -142.674,60.3 -138.264,55.89 J12.17@-138.175,55.89
F\A\U\L\T\_O\C\_S1: C37.2 R31.1 R204.2 | length 83.6
  Top Layer w0.25: v1(-203,93) -203,91.929 C37.2@-202.997,91.926 R204.2@-201.219,91.926 -201.051,91.926 R204.2@-200.975,91.85 ; v1@-136.9,112.4 -136.7,112.6 R31.1@-135.7,112.6
  Layer 2 w0.25: v1(-202.5,97.4) -200.6,99.3 v1@-200.4,99.3 ; v1(-166.825,113.457) -166.785,113.417 -154.521,113.417 -154.169,113.066 -137.766,113.066 v1(-137,112.3)
  Bottom Layer w0.25: v1(-203,93) -202.5,93.5 v1(-202.5,97.4) ; v1@-200.369,99.5 -200.3,99.569 -200.3,102.502 -197.502,105.3 -187.248,105.3 -186.869,104.921 -185.079,104.921 -177.662,112.338 -169.903,112.338 -168.819,113.422 -167.899,113.422 -167.864,113.457 v1(-166.825,113.457)
  other v1: -200.325,99.45
F\A\U\L\T\_O\C\_S1_init: R32.2 U6.4 | length 1.6
  Top Layer w0.25: R32.2@-109.7,110.8 -108.175,110.8 U6.4@-108.125,110.75
F\A\U\L\T\_O\C\_S2_init: R203.1 U25.4 | length 105.8
  Top Layer w0.25: v1(-198.725,72.15) -198.725,73.29 R203.1@-198.69,73.325 ; v1(-142,94.113) -141.951,94.162 -141.438,94.162 -140.949,94.651 -138.349,94.651 -137.161,95.839 -136.999,95.839 -136.759,96.079 -133.987,96.079 -133.793,95.885 -124.485,95.885 -123.879,95.279 U25.4@-121.801,95.279
  Layer 2 w0.25: v1(-193.7,76) -194.329,76.629 -196.819,76.629 -197.577,75.871 -199.619,75.871 -199.929,76.181 -199.929,76.619 -196.609,79.939 v1(-192.811,79.939) ; v1@-192.75,80 -192.761,80.011 -192.761,80.059 -192.75,80.07 -192.75,80.25 -190.6,82.4 -159.777,82.4 -159.223,82.954 v1(-154.325,82.954)
  Bottom Layer w0.25: v1(-198.725,72.15) -194.85,72.15 -193.7,73.3 v1(-193.7,76) ; v1(-154.325,82.954) -150.419,82.954 -147.098,86.275 -145.696,86.275 -144.746,87.225 -144.746,91.367 v1(-142,94.113)
F\A\U\L\T\_O\C\_S3: C83.2 R65.1 R206.2 | length 216.1
  Top Layer w0.25: C83.2@-200.582,95.598 R206.2@-198.827,95.598 ; R206.2@-198.65,95.55 v1(-198.65,96.8) ; v1(-174.062,92.177) -162.494,80.608 -162.342,80.608 v1(-162.293,80.559) ; R65.1@-34.79,84.921 -34.69,84.821 -34.69,83.746 v1@-34.715,83.721
  Bottom Layer w0.25: v1(-198.65,96.8) -196.25,94.4 -195.166,94.4 -195.141,94.375 -179.375,94.375 -177.177,92.177 v1(-174.062,92.177) ; v1@-162.35,80.609 -160.591,78.85 -158.85,78.85 -151.829,71.829 -149.581,71.829 -139.002,61.25 -137.748,61.25 -137.644,61.146 -137.206,61.146 -137.102,61.25 -123.302,61.25 -121.952,59.9 -114.476,59.9 -113.026,58.45 -105.55,58.45 -93.6,46.5 -53.286,46.5 -33.89,65.896 -33.89,82.846 v1(-34.69,83.646)
F\A\U\L\T\_O\C\_S3_init: R66.2 U13.4 | length 1.5
  Top Layer w0.25: R66.2@-56.29,97.321 -56.24,97.371 U13.4@-56.24,98.846
F\A\U\L\T\_O\C\_S4_init: R205.1 U26.4 | length 248.3
  Top Layer w0.25: R205.1@-196.83,77.289 -196.089,77.289 -195.8,77 v1(-195.8,76.1) ; v1(-163.525,86.625) -163.525,84.025 -162.046,82.546 -159.346,82.546 -151.216,74.416 -142.784,74.416 v1@-142.65,74.55 ; v1(-120.1,63.75) -120.1,60.87 -119.9,60.67 v1(-119.9,60.6) ; v1@-35.715,114.971 -35.69,114.996 -35.69,116.246 U26.4@-35.715,116.271
  Layer 2 w0.25: v1(-168.1,85) -165.15,85 v1(-163.525,86.625)
  Bottom Layer w0.25: v1(-195.8,76.1) -193.996,77.904 -180.356,77.904 -179.298,76.846 -176.193,76.846 -176.093,76.946 -175.655,76.946 -175.555,76.846 -173.952,76.846 -169.027,81.771 -169.027,81.793 -168.717,82.103 -168.695,82.103 -168.1,82.698 v1(-168.1,85) ; v1(-142.65,74.475) -138.448,74.475 -137.498,73.525 -135.783,73.525 -133.558,71.3 -123.566,71.3 -121.704,69.438 -121.704,65.354 v1(-120.1,63.75) ; v1(-119.9,60.6) -106.7,60.6 -94.4,48.3 -53.486,48.3 -35.39,66.396 -35.39,89.647 -35.419,89.675 -35.419,114.669 v1@-35.773,115.023
  other v1: -35.69,114.971
F\A\U\L\T\_O\C\_S5: C36.2 R28.1 R207.2 | length 82.9
  Top Layer w0.25: v1(-199.6,93) -199.2,92.6 C36.2@-199.2,91.85 ; C36.2@-199.116,91.826 R207.2@-197.338,91.826 -197.249,91.826 R207.2@-197.2,91.875 ; v1@-137.1,114 -136.93,114 -136.805,114.125 R28.1@-135.7,114.125
  Layer 2 w0.25: v1(-200.8,97.4) -200.091,98.109 -200.091,98.936 -199.383,99.644 v1(-199.383,99.679) ; v1(-199.4,101.6) -197.8,103.2 -195.55,103.2 -195,103.75 -193.653,103.75 -193.103,103.2 -185.518,103.2 -175.296,113.422 -167.609,113.422 -166.882,114.149 -148.694,114.149 -148.045,113.5 -137.695,113.5 -137.095,114.1 v1(-137.025,114.1)
  Bottom Layer w0.25: v1(-200.8,97.4) -200.8,94.2 v1(-199.6,93) ; v1(-199.4,101.6) -199.391,101.591 -199.391,99.688 v1(-199.383,99.679)
F\A\U\L\T\_O\C\_S5_init: R29.2 U7.4 | length 1.5
  Top Layer w0.25: R29.2@-113.8,117.75 U7.4@-112.275,117.75
F\A\U\L\T\_O\C\_S6: C82.2 R63.1 R208.2 | length 205.4
  Top Layer w0.25: v1(-197.85,97.65) -196.825,97.65 C82.2@-196.8,97.675 ; C82.2@-196.75,97.525 -196.699,97.474 R208.2@-196.699,95.576 ; v1(-173.307,92.193) -173.255,92.193 -162.312,81.249 -162.149,81.249 v1(-162.1,81.2) ; v1@-36.04,80.421 -36.015,80.446 -36.015,81.646 R63.1@-36.04,81.671
  Bottom Layer w0.25: v1(-197.85,97.65) -194.975,94.775 -178.073,94.775 -176.048,92.75 -173.796,92.75 -173.307,92.261 v1(-173.307,92.193) ; v1(-162.1,81.2) -160.15,79.25 -158.625,79.25 -151.604,72.229 -142.406,72.229 -135.998,65.821 -123.648,65.821 -119.227,61.4 -106.3,61.4 -94.9,50 -54.511,50 -36.015,68.496 v1(-36.015,80.321)
F\A\U\L\T\_O\C\_S6_init: R64.2 U14.4 | length 1.6
  Top Layer w0.25: U14.4@-63.29,87.621 -63.19,87.721 -61.84,87.721 R64.2@-61.74,87.621
F\A\U\L\T\_S1: C245.2 R237.2 U2.46 U6.1 | length 21.9
  Top Layer w0.25: U6.1@-105.3,108.9 -105.1,108.9 -104.925,108.725 -104.925,108.646 -104.779,108.5 C245.2@-103.6,108.5 R237.2@-103.6,107.15 ; v1@-103.625,105.925 -103.6,105.95 R237.2@-103.6,107 ; v1(-99.504,103.382) -99.455,103.332 -98.93,103.332 -98.635,103.038 v1@-97.312,103.038
  Layer 1 w0.25: v1(-103.6,105.85) -103.15,105.85 -102.621,106.379 -101.379,106.379 -100.85,105.85 -99.75,104.75 -99.75,103.657 -99.504,103.411 v1(-99.504,103.382) ; v1@-97.3,103.075 -97.3,103.045 -97.151,102.896 -97.121,102.896 -92.175,97.95 v1(-92.175,97.2)
  Bottom Layer w0.25: U2.46@-92.475,96.375 -92.45,96.4 -92.45,96.855 -92.175,97.13 v1(-92.175,97.2)
  other v1: -97.35,103.025
F\A\U\L\T\_S2_init: C253.2 R335.2 U8.46 U25.1 | length 16.6
  Top Layer w0.25: U25.1@-119.051,93.379 -119.043,93.371 -118.399,93.371 -118.17,93.6 v1(-118.1,93.6) ; v1@-118.214,93.644 -118.075,93.644 -117.886,93.456 -117.525,93.456 -117.204,93.135 C253.2@-117.204,93.071 ; R335.2@-117.15,91.725 -117.15,93.013 C253.2@-117.15,93.125
  Layer 2 w0.25: v1(-118.1,93.6) -116.6,93.6 -113.721,96.479 -110.781,96.479 -110.552,96.25 -108.65,96.25 -108.225,96.675 v1(-108.225,97.125)
  Bottom Layer w0.25: U8.46@-108.258,96.025 -108.242,96.041 -108.242,97.108 v1(-108.225,97.125)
